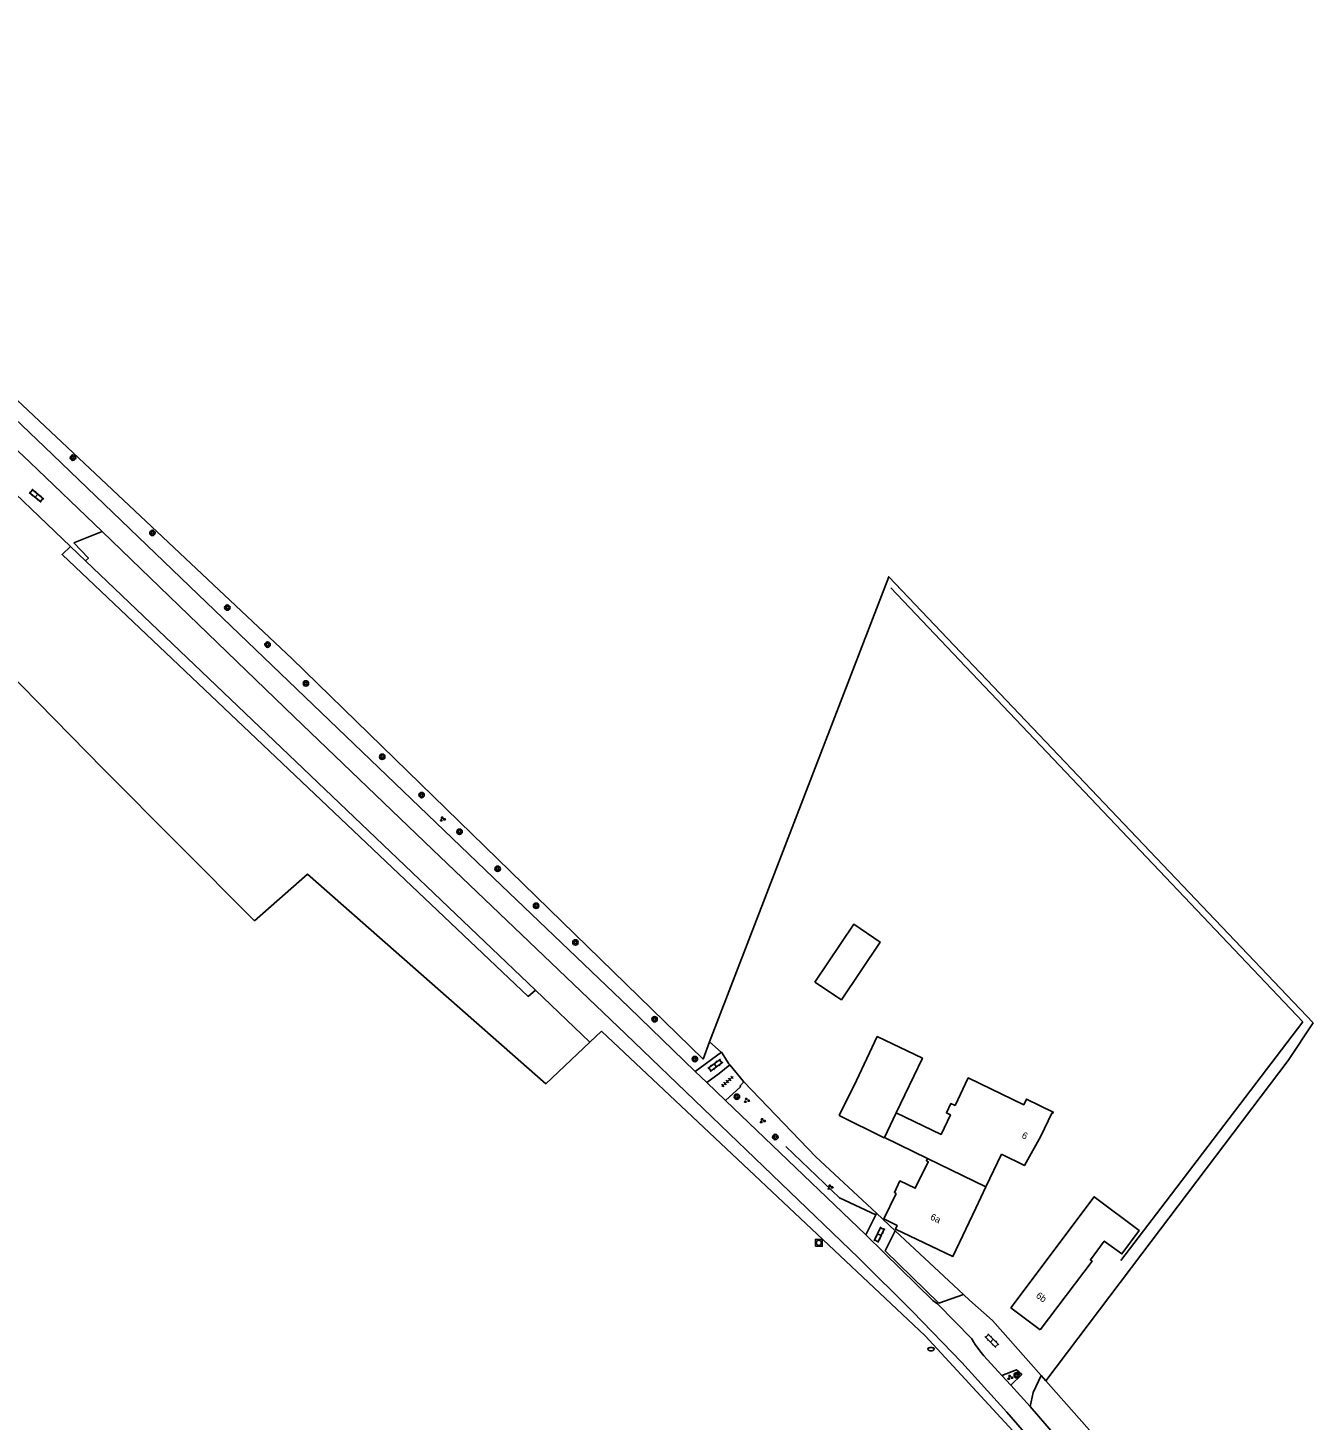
# Model space of a CAD drawing. Extents: x 124000 to 129000, y 395500 to 397503.
# Drawn here: x 126314 to 126504, y 396968.6 to 397174.5 of the extents above; entities that cross this region are included whole.
import ezdxf

# ---------------------------------------------------------------- set-up
doc = ezdxf.new("R2010")
doc.units = 0
for name, color, linetype in [('gg-afsc-erfafscheiding', 7, 'Continuous'), ('gg-anno-huisnummerreeks BGT', 7, 'Continuous'), ('gg-bbg-bijgebouw', 7, 'Continuous'), ('gg-bbg-hoofdgebouw', 7, 'Continuous'), ('gg-bbg-tussenscheiding', 7, 'Continuous'), ('gg-knt-bronhoudergrens', 7, 'Continuous'), ('gg-knt-verharding', 7, 'Continuous'), ('gg-kntw-midden sloot', 7, 'Continuous'), ('gt-grn-groengrens', 7, 'Continuous'), ('gt-grn-weggrens', 7, 'Continuous'), ('gt-symb-boom', 7, 'Continuous'), ('gt-symb-brandkraan', 7, 'Continuous'), ('gt-symb-groenvak', 7, 'Continuous'), ('gt-symb-klinker verharding', 7, 'Continuous'), ('gt-symb-rioolschacht', 7, 'Continuous'), ('gt-symb-tegel verharding', 7, 'Continuous')]:
    doc.layers.add(name, color=color, linetype=linetype)

# ---------------------------------------------------------------- blocks, each defined once
blk = doc.blocks.new('gt0-KL1')
at = {"layer": 'gt-symb-klinker verharding'}
for p, q in [((-1.15, 0.3), (1.15, 0.3)), ((-1, -0.3), (-1, 0.3)), ((-0.5, 0.3), (-0.5, 0.45)), ((0, -0.3), (0, 0.3)), ((0.5, 0.3), (0.5, 0.45)), ((1, -0.3), (1, 0.3)), ((-1.15, -0.3), (1.15, -0.3)), ((-0.5, -0.45), (-0.5, -0.3)), ((0.5, -0.45), (0.5, -0.3))]:
    blk.add_line(p, q, dxfattribs=at)
blk = doc.blocks.new('gt0-BOOM')
at = {"layer": 'gt-symb-boom'}
for radius in [0.4, 0.2]:
    blk.add_circle((0, 0), radius, dxfattribs=at)
blk = doc.blocks.new('gt0-GRVAK')
at = {"layer": 'gt-symb-groenvak'}
for p, q in [((-0.11, 0.19), (-0.23, 0.24)), ((-0.18, 0.15), (0.09, 0.15)), ((-0.09, 0.21), (-0.16, 0.32)), ((-0.05, 0.21), (-0.05, 0.39)), ((0, 0.21), (0.06, 0.32)), ((0.01, 0.19), (0.13, 0.24)), ((0.26, -0.05), (0.2, 0.06)), ((0.3, -0.05), (0.3, 0.13)), ((0.35, -0.05), (0.41, 0.06)), ((-0.25, -0.23), (-0.36, -0.18)), ((-0.32, -0.26), (-0.05, -0.26)), ((-0.23, -0.21), (-0.29, -0.09)), ((-0.18, -0.2), (-0.18, -0.02)), ((-0.14, -0.21), (-0.07, -0.09)), ((-0.12, -0.23), (0, -0.18)), ((0.24, -0.07), (0.12, -0.02)), ((0.17, -0.11), (0.44, -0.11)), ((0.37, -0.07), (0.49, -0.02))]:
    blk.add_line(p, q, dxfattribs=at)
blk = doc.blocks.new('gt0-TEG1')
at = {"layer": 'gt-symb-tegel verharding'}
for p, q in [((-1.12, 0), (1.13, 0)), ((-0.9, -0.25), (-0.9, 0.25)), ((-0.45, -0.25), (-0.45, 0.25)), ((0, -0.25), (0, 0.25)), ((0.45, -0.25), (0.45, 0.25)), ((0.9, -0.25), (0.9, 0.25))]:
    blk.add_line(p, q, dxfattribs=at)
blk = doc.blocks.new('gt0-RS')
at = {"layer": 'gt-symb-rioolschacht'}
blk.add_lwpolyline([(-0.5, -0.5), (0.5, -0.5), (0.5, 0.5), (-0.5, 0.5)], close=True, dxfattribs=at)
blk.add_circle((0, 0), 0.375, dxfattribs=at)
blk = doc.blocks.new('gt0-BR')
at = {"layer": 'gt-symb-brandkraan'}
for centre, radius, start, end in [((-0.24, 0), 0.206, 107.5669, 252.4331), ((0.6, -2.66), 3, 106.892, 107.5669), ((0, -0.69), 0.938, 73.108, 106.892), ((-0.6, -2.66), 3, 72.4331, 73.108), ((0.24, 0), 0.206, 287.567, 72.4331), ((0.6, 2.66), 3, 252.4331, 253.108), ((0, 0.69), 0.938, 253.108, 286.8921), ((-0.6, 2.66), 3, 286.8921, 287.567)]:
    blk.add_arc(centre, radius, start, end, dxfattribs=at)

msp = doc.modelspace()

# ---------------------------------------------------------------- linework, layer by layer
at = {"layer": 'gg-afsc-erfafscheiding'}
msp.add_lwpolyline([(126439.36, 396999.01), (126433.99, 397001.53), (126426.09, 397009.09)], dxfattribs=at)
at = {"layer": 'gg-bbg-bijgebouw'}
for points in [[(126430.35, 397033.41), (126434.28, 397030.8), (126440.02, 397039.33), (126436.11, 397041.96), (126430.35, 397033.41)], [(126442.4, 397014.06), (126446.28, 397022.14), (126439.58, 397025.36), (126436.5, 397018.87), (126433.94, 397013.69)], [(126440.65, 397010.43), (126440.63, 397010.4), (126433.94, 397013.69)]]:
    msp.add_lwpolyline(points, dxfattribs=at)
at = {"layer": 'gg-bbg-hoofdgebouw'}
for p, q in [((126447.01, 397007.33), (126440.65, 397010.43)), ((126457.95, 397007.97), (126455.67, 397003.16)), ((126455.67, 397003.16), (126454.18, 397000)), ((126442.39, 397002.17), (126440.56, 396998.41)), ((126459.32, 396985.23), (126463.67, 396981.97))]:
    msp.add_line(p, q, dxfattribs=at)
for points in [[(126457.95, 397007.97), (126461.34, 397006.28), (126463.77, 397010.65), (126465.4, 397014.05), (126465.52, 397014), (126465.61, 397014.2), (126461.65, 397016.1), (126461.26, 397015.28), (126453.04, 397019.23), (126451.09, 397015.17), (126450.49, 397015.45), (126449.82, 397014.06), (126450.42, 397013.77), (126449.03, 397010.88), (126442.4, 397014.06)], [(126442.39, 397002.17), (126442.14, 397002.3), (126442.95, 397004.01), (126445.22, 397002.92), (126447.12, 397006.85), (126446.85, 397006.99), (126447.01, 397007.33)], [(126463.67, 396981.97), (126471.36, 396992.14), (126471.12, 396992.32), (126473.16, 396995.12), (126475.77, 396993.21), (126478.31, 396996.68), (126471.65, 397001.67), (126459.32, 396985.23)], [(126454.18, 397000), (126450.79, 396992.84), (126442.29, 396996.87), (126442.53, 396997.43), (126440.56, 396998.41)]]:
    msp.add_lwpolyline(points, dxfattribs=at)
at = {"layer": 'gg-bbg-tussenscheiding'}
for p, q in [((126440.65, 397010.43), (126442.4, 397014.06)), ((126447.01, 397007.33), (126455.67, 397003.16))]:
    msp.add_line(p, q, dxfattribs=at)
at = {"layer": 'gg-knt-bronhoudergrens'}
msp.add_line((126398.82, 397026.17), (126397.11, 397024.55), dxfattribs=at)
for points in [[(126252.1, 397174.52), (126303.2, 397128.09), (126353.01, 397081.26), (126413.83, 397022.02), (126414.81, 397024.58)], [(126414.81, 397024.58), (126441.29, 397093.35), (126504.04, 397027.38)], [(126242.71, 397072.69), (126308.21, 397082.15), (126325.15, 397064.93), (126347.51, 397042.45)], [(126397.11, 397024.55), (126390.57, 397018.38), (126355.34, 397049.36), (126347.51, 397042.45)], [(126464.5, 396974.47), (126478.69, 396993.22), (126500.34, 397021.82), (126504.04, 397027.38)], [(126473.18, 396952.37), (126446.7, 396981.11), (126398.82, 397026.17)]]:
    msp.add_lwpolyline(points, dxfattribs=at)
at = {"layer": 'gg-knt-verharding'}
for p, q in [((126324.99, 397100.03), (126320.8, 397098.35)), ((126412.65, 397020.19), (126416.54, 397023.04)), ((126414.37, 397018.54), (126412.65, 397020.19)), ((126417.17, 397015.88), (126414.37, 397018.54)), ((126417.17, 397015.88), (126437.92, 396996.02)), ((126437.92, 396996.02), (126439.36, 396999.01)), ((126439.36, 396999.01), (126439.46, 396999.23)), ((126459.32, 396973.83), (126458.03, 396975.23)), ((126459.32, 396973.83), (126462.18, 396970.67)), ((126462.62, 396972.7), (126463.84, 396975.22)), ((126462.18, 396970.67), (126462.62, 396972.7))]:
    msp.add_line(p, q, dxfattribs=at)
for points in [[(126412.65, 397020.19), (126402.84, 397029.7), (126384.03, 397047.69), (126340.43, 397089.56), (126316.44, 397112.57), (126296.69, 397131.4), (126283.17, 397143.79), (126268.6, 397156.78), (126249.68, 397173.52)], [(126324.99, 397100.03), (126314.29, 397110.31), (126307.36, 397116.82)], [(126472.35, 396953.88), (126467.53, 396959.7), (126458.73, 396969.82), (126452.09, 396977.17), (126444.82, 396984.68), (126436.8, 396992.63), (126402.35, 397025.76), (126373.84, 397053.02), (126353.38, 397072.64), (126324.99, 397100.03)], [(126320.8, 397098.35), (126322.95, 397096.08), (126322.54, 397095.69)], [(126414.37, 397018.54), (126416.24, 397019.91), (126417.8, 397021.17)], [(126417.17, 397015.88), (126419.37, 397017.94), (126419.3, 397018.05), (126419.85, 397018.67)], [(126452.32, 396987.23), (126448.7, 396985.95), (126440.74, 396993.65), (126442.26, 396996.61)], [(126458.03, 396975.23), (126455.35, 396978.14), (126454.76, 396978.88), (126454.05, 396979.81), (126453.81, 396980.2), (126453.58, 396980.64), (126448.5, 396985.84), (126447.8, 396986.34), (126440.6, 396993.36), (126437.92, 396996.02)], [(126458.03, 396975.23), (126460.19, 396976.09), (126460.96, 396975.39), (126459.32, 396973.83)], [(126485.91, 396942.48), (126478.56, 396951.43), (126473.37, 396957.63), (126467.41, 396964.61), (126462.18, 396970.67)]]:
    msp.add_lwpolyline(points, dxfattribs=at)
at = {"layer": 'gg-kntw-midden sloot'}
for p, q in [((126502.51, 397027.52), (126441.61, 397091.69)), ((126481.52, 397000), (126502.51, 397027.52)), ((126475.59, 396992.22), (126481.52, 397000))]:
    msp.add_line(p, q, dxfattribs=at)
at = {"layer": 'gt-grn-groengrens'}
for p, q in [((126320.29, 397097.84), (126322.54, 397095.69)), ((126322.54, 397095.69), (126389.06, 397032.23)), ((126389.06, 397032.23), (126397.11, 397024.55)), ((126414.81, 397024.58), (126416.52, 397023.07)), ((126419.82, 397018.7), (126419.85, 397018.67)), ((126439.46, 396999.23), (126442.26, 396996.61)), ((126442.26, 396996.61), (126452.32, 396987.23)), ((126464.5, 396974.47), (126463.84, 396975.22))]:
    msp.add_line(p, q, dxfattribs=at)
for points in [[(126320.29, 397097.84), (126319.07, 397096.63), (126387.96, 397031.29), (126389.06, 397032.23)], [(126419.85, 397018.67), (126430.52, 397007.56), (126439.46, 396999.23)], [(126489.12, 396945.14), (126473.42, 396963.95), (126473.64, 396964.14), (126464.5, 396974.47)]]:
    msp.add_lwpolyline(points, dxfattribs=at)
at = {"layer": 'gt-grn-weggrens'}
for p, q in [((126416.52, 397023.07), (126416.54, 397023.04)), ((126417.8, 397021.17), (126419.82, 397018.7))]:
    msp.add_line(p, q, dxfattribs=at)
for points in [[(126305.65, 397113.83), (126308.57, 397111.16), (126307.51, 397110.03), (126320.29, 397097.84)], [(126416.54, 397023.04), (126417.67, 397021.33), (126417.8, 397021.17)], [(126463.84, 396975.22), (126456.64, 396983.36), (126453.25, 396986.36), (126452.32, 396987.23)]]:
    msp.add_lwpolyline(points, dxfattribs=at)

# ---------------------------------------------------------------- block references
at = {"layer": 'gt-symb-boom'}
for p in [(126320.67, 397110.96), (126332.41, 397099.83), (126343.49, 397088.79), (126349.45, 397083.31), (126366.39, 397066.73), (126372.22, 397061.07), (126377.83, 397055.65), (126383.46, 397050.17), (126389.15, 397044.7), (126394.97, 397039.27), (126406.67, 397027.92), (126412.63, 397022.03), (126418.83, 397016.46), (126424.52, 397010.5), (126460.22, 396975.28)]:
    msp.add_blockref('gt0-BOOM', p, dxfattribs=at)
at = {"layer": 'gt-symb-boom', "rotation": -67.17745934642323}
msp.add_blockref('gt0-BOOM', (126355.11, 397077.57), dxfattribs=at)
at = {"layer": 'gt-symb-brandkraan'}
msp.add_blockref('gt0-BR', (126447.54, 396979.14), dxfattribs=at)
at = {"layer": 'gt-symb-groenvak'}
for p in [(126375.31, 397057.52), (126420.27, 397015.93), (126422.61, 397012.91), (126432.62, 397003.09), (126459.21, 396974.96)]:
    msp.add_blockref('gt0-GRVAK', p, dxfattribs=at)
at = {"layer": 'gt-symb-klinker verharding'}
for p, rotation in [((126315.27, 397105.33), -39.196688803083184), ((126415.65, 397021.1), 36.789699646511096), ((126439.9, 396996.05), 64.02428534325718), ((126456.54, 396980.38), -45.000000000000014)]:
    msp.add_blockref('gt0-KL1', p, dxfattribs=dict(at, rotation=rotation))
at = {"layer": 'gt-symb-rioolschacht'}
msp.add_blockref('gt0-RS', (126430.95, 396994.85), dxfattribs=at)
at = {"layer": 'gt-symb-tegel verharding', "rotation": 41.75724702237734}
msp.add_blockref('gt0-TEG1', (126417.43, 397018.72), dxfattribs=at)

# ---------------------------------------------------------------- texts
at = {"layer": 'gg-anno-huisnummerreeks BGT'}
for s, rotation, p in [('6', 333.5, (126460.86, 397010.43)), ('6a', 334.7, (126447.34, 396998.35)), ('6b', 323.1, (126462.97, 396986.87))]:
    msp.add_text(s, height=1, rotation=rotation, dxfattribs=at).set_placement(p)

doc.saveas('drawing.dxf')
